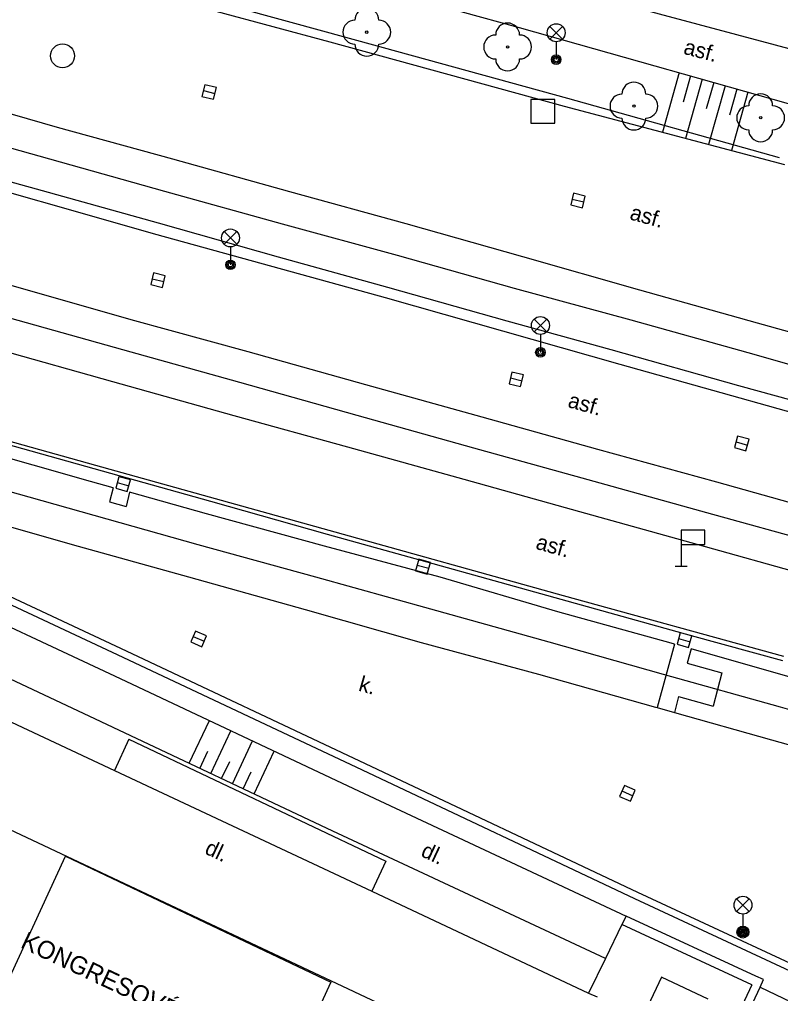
# Model space of a CAD drawing. Extents: x -600309 to -598967, y -1161267 to -1160292.
# Drawn here: x -599908.39 to -599876.57, y -1161220.83 to -1161180.1 of the extents above; entities that cross this region are included whole.
import ezdxf

# ---------------------------------------------------------------- set-up
doc = ezdxf.new("R2010")
doc.units = 0
for name, color, linetype in [('Level 11', 7, 'Continuous'), ('Level 13', 7, 'Continuous'), ('Level 14', 7, 'Continuous'), ('Level 15', 7, 'Continuous'), ('Level 22', 7, 'Continuous'), ('Level 25', 7, 'Continuous'), ('Level 26', 7, 'Continuous'), ('Level 27', 7, 'Continuous'), ('Level 33', 7, 'Continuous'), ('Level 34', 7, 'Continuous'), ('Level 40', 7, 'Continuous'), ('Level 41', 7, 'Continuous'), ('Level 5', 7, 'Continuous'), ('Level 7', 7, 'Continuous'), ('Level 9', 7, 'Continuous')]:
    doc.layers.add(name, color=color, linetype=linetype)

msp = doc.modelspace()

# ---------------------------------------------------------------- linework, layer by layer
at = {"layer": 'Level 11'}
for points in [[(-599863.64, -1161184.68), (-599889.92, -1161177.65), (-599907.2809, -1161172.7877), (-599916.52, -1161170.2), (-599932.76, -1161165.82), (-599934.95, -1161165.24), (-599946.09, -1161162.38), (-599957.33, -1161160.21), (-599967.01, -1161157.86)], [(-599930.64, -1161168.52), (-599923.55, -1161170.36), (-599921.2022, -1161171.0138), (-599908, -1161174.69), (-599894.81, -1161178.4099), (-599887.5, -1161180.43), (-599874.9699, -1161183.98)], [(-599930.45, -1161171.5), (-599922.2, -1161173.73), (-599913.48, -1161176.08), (-599904.95, -1161178.45), (-599895.42, -1161181.04), (-599885.61, -1161183.7199), (-599876.4099, -1161186.17)], [(-599939.95, -1161175.2), (-599936.36, -1161176.23), (-599931.17, -1161177.71), (-599926.29, -1161179.09), (-599921.4099, -1161180.4699), (-599916.57, -1161181.81), (-599911.32, -1161183.31), (-599906.82, -1161184.6), (-599901.99, -1161185.93), (-599897.1, -1161187.3), (-599892.24, -1161188.63), (-599887.36, -1161190.01), (-599882.46, -1161191.4), (-599877.54, -1161192.78), (-599872.64, -1161194.15), (-599870.4099, -1161194.77)], [(-599940.73, -1161177.89), (-599937.07, -1161178.9099), (-599931.93, -1161180.36), (-599927.03, -1161181.75), (-599922.07, -1161183.1599), (-599917.31, -1161184.49), (-599912.24, -1161185.93), (-599907.44, -1161187.25), (-599902.59, -1161188.61), (-599897.58, -1161190.02), (-599893, -1161191.29), (-599888.01, -1161192.7), (-599883.67, -1161193.9), (-599878.32, -1161195.4), (-599872.33, -1161197.05)], [(-599941.83, -1161181.93), (-599937.6, -1161183.12), (-599932.81, -1161184.4699), (-599927.93, -1161185.83), (-599923.11, -1161187.2), (-599918.2, -1161188.58), (-599913.23, -1161189.9699), (-599908.46, -1161191.3), (-599903.74, -1161192.64), (-599898.84, -1161193.99), (-599893.93, -1161195.37), (-599889.06, -1161196.7199), (-599884.2199, -1161198.07), (-599879.25, -1161199.44), (-599873.43, -1161201.06)], [(-599875.4699, -1161203.34), (-599880.06, -1161202.06), (-599884.96, -1161200.69), (-599889.8, -1161199.33), (-599894.6599, -1161197.99), (-599899.42, -1161196.67), (-599904.49, -1161195.25), (-599909.26, -1161193.9099), (-599913.99, -1161192.59), (-599919, -1161191.18), (-599923.76, -1161189.83), (-599928.58, -1161188.4699), (-599933.44, -1161187.11), (-599938.29, -1161185.74), (-599942.58, -1161184.57)], [(-599943.62, -1161188.24), (-599939.48, -1161189.38), (-599934.7199, -1161190.69), (-599929.63, -1161192.12), (-599924.84, -1161193.46), (-599919.9, -1161194.81), (-599915.13, -1161196.14), (-599910.12, -1161197.53), (-599905.29, -1161198.87), (-599900.4099, -1161200.24), (-599895.52, -1161201.62), (-599891.36, -1161202.78), (-599885.75, -1161204.34), (-599880.31, -1161205.86), (-599876.49, -1161206.9099)], [(-599943.57, -1161188.06), (-599943.4099, -1161188.13), (-599934.69, -1161190.53), (-599924.78, -1161193.29), (-599915.04, -1161195.99), (-599905.21, -1161198.73), (-599895.46, -1161201.46), (-599885.6599, -1161204.19), (-599876.44, -1161206.73)], [(-599904.48, -1161199.68), (-599905.42, -1161199.42), (-599910.23, -1161198.06), (-599913.13, -1161197.25)], [(-599904.48, -1161199.68), (-599904.63, -1161200.27)], [(-599903.79, -1161199.87), (-599903.93, -1161200.4699)], [(-599881, -1161206.2199), (-599881.14, -1161206.18), (-599885.88, -1161204.87), (-599890.8, -1161203.42), (-599895.64, -1161202.13), (-599900.57, -1161200.77), (-599903.79, -1161199.87)], [(-599904.63, -1161200.27), (-599903.93, -1161200.4699)], [(-599911.03, -1161200.67), (-599906.19, -1161202.06), (-599901.32, -1161203.4), (-599896.45, -1161204.77), (-599891.59, -1161206.15), (-599886.69, -1161207.48), (-599881.8, -1161208.85), (-599881.73, -1161208.87)], [(-599789.95, -1161232.9), (-599790.9699, -1161236.06), (-599800.96, -1161233.11), (-599809.71, -1161230.49), (-599818.68, -1161230.93), (-599828.53, -1161231.42), (-599840.03, -1161232.03), (-599849.05, -1161232.52), (-599855.12, -1161229.63), (-599865.36, -1161224.89), (-599873.32, -1161221.2199), (-599882.6599, -1161216.87), (-599894.05, -1161211.49), (-599904.05, -1161206.78), (-599911.83, -1161203.14), (-599911.7, -1161202.87)], [(-599789.95, -1161232.9), (-599790.24, -1161232.81), (-599791.17, -1161235.69), (-599800.87, -1161232.82), (-599809.67, -1161230.19), (-599818.7, -1161230.63), (-599828.55, -1161231.12), (-599840.05, -1161231.73), (-599848.99, -1161232.2199), (-599854.99, -1161229.36), (-599865.23, -1161224.62), (-599873.19, -1161220.95), (-599882.53, -1161216.6), (-599893.92, -1161211.2199), (-599903.92, -1161206.51), (-599911.7, -1161202.87)], [(-599881, -1161206.2199), (-599881.73, -1161208.87)], [(-599880.31, -1161206.42), (-599880.4699, -1161207.02)], [(-599876.1599, -1161207.6), (-599880.31, -1161206.42)], [(-599880.4699, -1161207.02), (-599879.02, -1161207.42)], [(-599879.02, -1161207.42), (-599879.39, -1161208.81)], [(-599880.83, -1161208.4099), (-599881, -1161209.08)], [(-599880.83, -1161208.4099), (-599879.39, -1161208.81)], [(-599881.73, -1161208.87), (-599881, -1161209.08)], [(-599881, -1161209.08), (-599876.95, -1161210.2199), (-599872.07, -1161211.59), (-599867.2, -1161212.95), (-599862.3, -1161214.31), (-599857.42, -1161215.7199), (-599852.56, -1161217.08), (-599842.77, -1161219.65)], [(-599903.82, -1161210.2), (-599904.42, -1161211.5)], [(-599903.82, -1161210.2), (-599893.07, -1161215.29)], [(-599915.56, -1161210.8), (-599886, -1161224.71)], [(-599893.07, -1161215.29), (-599893.6599, -1161216.55)], [(-599883.2, -1161217.95), (-599883.89, -1161219.36)], [(-599883.89, -1161219.36), (-599884.6, -1161220.81)], [(-599881.54, -1161220.15), (-599891.18, -1161240.58)], [(-599879.6, -1161221.06), (-599881.54, -1161220.15)], [(-599877.42, -1161220.56), (-599873.86, -1161222.27)]]:
    msp.add_lwpolyline(points, dxfattribs=at)
at = {"layer": 'Level 13'}
for points in [[(-599911.67, -1161184.6599), (-599907.14, -1161185.93), (-599902.33, -1161187.28), (-599897.4099, -1161188.64), (-599892.6, -1161189.96), (-599887.71, -1161191.33), (-599882.83, -1161192.6599), (-599877.93, -1161194.02), (-599873.05, -1161195.42), (-599867.81, -1161196.87), (-599863.07, -1161198.19), (-599858.15, -1161199.56), (-599853.34, -1161200.88), (-599848.55, -1161202.23), (-599843.71, -1161203.58), (-599838.78, -1161204.96), (-599833.98, -1161206.3), (-599829.05, -1161207.68), (-599824.28, -1161209.01), (-599814.6, -1161211.7199)], [(-599939.98, -1161191.14), (-599935.24, -1161192.5), (-599930.2199, -1161193.87), (-599925.33, -1161195.24), (-599920.48, -1161196.58), (-599915.56, -1161197.96), (-599910.63, -1161199.32), (-599905.82, -1161200.68), (-599900.94, -1161202.06), (-599896.01, -1161203.4099), (-599891.2, -1161204.75), (-599886.26, -1161206.12), (-599881.48, -1161207.48), (-599876.58, -1161208.84), (-599871.7, -1161210.24), (-599866.85, -1161211.58), (-599861.95, -1161212.96), (-599857, -1161214.35), (-599852.12, -1161215.73), (-599847.21, -1161217.08), (-599842.49, -1161218.27)], [(-599908.81, -1161192.58), (-599904.09, -1161193.9), (-599899.19, -1161195.27), (-599894.29, -1161196.65), (-599889.4099, -1161198.01), (-599884.62, -1161199.34), (-599879.6599, -1161200.7199), (-599875.02, -1161202), (-599869.7, -1161203.49), (-599864.88, -1161204.84), (-599860.39, -1161206.1), (-599855.17, -1161207.56), (-599850.4699, -1161208.87), (-599845.4699, -1161210.27), (-599840.67, -1161211.61), (-599835.69, -1161213), (-599831.84, -1161214.03)]]:
    msp.add_lwpolyline(points, dxfattribs=at)
at = {"layer": 'Level 14'}
for points in [[(-599912.06, -1161203.98), (-599904.42, -1161207.55), (-599894.43, -1161212.26), (-599883.03, -1161217.59)], [(-599883.89, -1161219.36), (-599895.29, -1161214.04), (-599904.9699, -1161209.4699), (-599912.84, -1161205.77)]]:
    msp.add_lwpolyline(points, dxfattribs=at)
at = {"layer": 'Level 15'}
for points in [[(-599880.81, -1161182.32), (-599881.51, -1161184.81)], [(-599880.33, -1161182.46), (-599880.64, -1161183.56)], [(-599879.85, -1161182.6), (-599880.54, -1161185.07)], [(-599879.36, -1161182.74), (-599879.68, -1161183.83)], [(-599878.89, -1161182.87), (-599879.58, -1161185.33)], [(-599878.4, -1161183.01), (-599878.71, -1161184.1)], [(-599877.93, -1161183.14), (-599878.62, -1161185.58)], [(-599901.3, -1161211.2), (-599900.45, -1161209.42)], [(-599900.39, -1161211.63), (-599899.55, -1161209.85)], [(-599899.49, -1161212.06), (-599898.65, -1161210.27)], [(-599900.85, -1161211.42), (-599900.51, -1161210.7)], [(-599898.58, -1161212.48), (-599897.74, -1161210.7)], [(-599899.94, -1161211.84), (-599899.6, -1161211.13)], [(-599899.04, -1161212.27), (-599898.7, -1161211.56)]]:
    msp.add_lwpolyline(points, dxfattribs=at)
at = {"layer": 'Level 22'}
for centre in [(-599893.87, -1161180.63), (-599887.98, -1161181.25), (-599882.7, -1161183.7199), (-599877.4, -1161184.21)]:
    msp.add_circle(centre, 0.05, dxfattribs=at)
for centre, start, end in [((-599893.87, -1161180.13), 0, 180), ((-599894.37, -1161180.63), 90, 270), ((-599893.37, -1161180.63), 270, 90), ((-599887.98, -1161180.75), 0, 180), ((-599888.48, -1161181.25), 90, 270), ((-599887.48, -1161181.25), 270, 90), ((-599893.87, -1161181.13), 180, 0), ((-599887.98, -1161181.75), 180, 0), ((-599882.7, -1161183.2199), 0, 180), ((-599883.2, -1161183.7199), 90, 270), ((-599882.2, -1161183.7199), 270, 90), ((-599877.4, -1161183.71), 0, 180), ((-599877.9, -1161184.21), 90, 270), ((-599876.9, -1161184.21), 270, 90), ((-599882.7, -1161184.2199), 180, 0), ((-599877.4, -1161184.71), 180, 0)]:
    msp.add_arc(centre, 0.5, start, end, dxfattribs=at)
at = {"layer": 'Level 25'}
for radius in [0.25, 0.2, 0.15, 0.1, 0.05]:
    msp.add_circle((-599878.14, -1161218.26), radius, dxfattribs=at)
at = {"layer": 'Level 26'}
msp.add_lwpolyline([(-599887.01, -1161184.44), (-599886.01, -1161184.44), (-599886.01, -1161183.44), (-599887.01, -1161183.44)], close=True, dxfattribs=at)
at = {"layer": 'Level 27'}
for p, q in [((-599900.7031, -1161183.0715), (-599900.2169, -1161183.1885)), ((-599885.2831, -1161187.6115), (-599884.7969, -1161187.7285)), ((-599902.8431, -1161190.9415), (-599902.3569, -1161191.0585)), ((-599887.8631, -1161195.0915), (-599887.3769, -1161195.2085)), ((-599878.4308, -1161197.7629), (-599877.9492, -1161197.8971)), ((-599904.3008, -1161199.4629), (-599903.8192, -1161199.5971)), ((-599891.7608, -1161202.9129), (-599891.2792, -1161203.0471)), ((-599901.1294, -1161205.9005), (-599900.6706, -1161206.0995)), ((-599880.8308, -1161205.9829), (-599880.3492, -1161206.1171)), ((-599883.1993, -1161212.3605), (-599882.7405, -1161212.5595))]:
    msp.add_line(p, q, dxfattribs=at)
for points in [[(-599900.7616, -1161183.3145), (-599900.2755, -1161183.4316), (-599900.1584, -1161182.9455), (-599900.6445, -1161182.8284)], [(-599885.3416, -1161187.8545), (-599884.8555, -1161187.9716), (-599884.7384, -1161187.4855), (-599885.2245, -1161187.3684)], [(-599902.9016, -1161191.1845), (-599902.4155, -1161191.3016), (-599902.2984, -1161190.8155), (-599902.7845, -1161190.6984)], [(-599887.9216, -1161195.3345), (-599887.4355, -1161195.4516), (-599887.3184, -1161194.9655), (-599887.8045, -1161194.8484)], [(-599878.498, -1161198.0037), (-599878.0163, -1161198.138), (-599877.882, -1161197.6563), (-599878.3637, -1161197.522)], [(-599904.368, -1161199.7037), (-599903.8863, -1161199.838), (-599903.752, -1161199.3563), (-599904.2337, -1161199.222)], [(-599891.828, -1161203.1537), (-599891.3463, -1161203.288), (-599891.212, -1161202.8063), (-599891.6937, -1161202.672)], [(-599901.2288, -1161206.1299), (-599900.7701, -1161206.3288), (-599900.5712, -1161205.8701), (-599901.0299, -1161205.6712)], [(-599880.898, -1161206.2237), (-599880.4163, -1161206.358), (-599880.282, -1161205.8763), (-599880.7637, -1161205.742)], [(-599883.2987, -1161212.5899), (-599882.84, -1161212.7888), (-599882.6411, -1161212.3301), (-599883.0998, -1161212.1312)]]:
    msp.add_lwpolyline(points, close=True, dxfattribs=at)
msp.add_circle((-599906.59, -1161181.62), 0.5, dxfattribs=at)
at = {"layer": 'Level 33'}
for p, q in [((-599886.215, -1161180.92), (-599885.685, -1161180.39)), ((-599886.215, -1161180.39), (-599885.685, -1161180.92)), ((-599885.95, -1161181.03), (-599885.95, -1161181.78)), ((-599899.835, -1161189.5), (-599899.305, -1161188.97)), ((-599899.835, -1161188.97), (-599899.305, -1161189.5)), ((-599899.57, -1161189.61), (-599899.57, -1161190.36)), ((-599886.875, -1161193.16), (-599886.345, -1161192.63)), ((-599886.875, -1161192.63), (-599886.345, -1161193.16)), ((-599886.61, -1161193.27), (-599886.61, -1161194.02)), ((-599878.405, -1161217.4), (-599877.875, -1161216.87)), ((-599878.405, -1161216.87), (-599877.875, -1161217.4)), ((-599878.14, -1161217.51), (-599878.14, -1161218.26))]:
    msp.add_line(p, q, dxfattribs=at)
for centre, radius in [((-599885.95, -1161180.655), 0.375), ((-599885.95, -1161181.78), 0.2), ((-599885.95, -1161181.78), 0.1445), ((-599885.95, -1161181.78), 0.0876), ((-599899.57, -1161189.235), 0.375), ((-599899.57, -1161190.36), 0.2), ((-599899.57, -1161190.36), 0.1445), ((-599899.57, -1161190.36), 0.0876), ((-599886.61, -1161192.895), 0.375), ((-599886.61, -1161194.02), 0.2), ((-599886.61, -1161194.02), 0.1445), ((-599886.61, -1161194.02), 0.0876), ((-599878.14, -1161217.135), 0.375)]:
    msp.add_circle(centre, radius, dxfattribs=at)
at = {"layer": 'Level 34'}
for p, q in [((-599880.73, -1161202.06), (-599880.73, -1161202.96)), ((-599880.98, -1161202.96), (-599880.48, -1161202.96))]:
    msp.add_line(p, q, dxfattribs=at)
msp.add_lwpolyline([(-599880.73, -1161202.06), (-599879.73, -1161202.06), (-599879.73, -1161201.46), (-599880.73, -1161201.46)], close=True, dxfattribs=at)
at = {"layer": 'Level 5'}
for points in [[(-599913.49, -1161207.25), (-599904.42, -1161211.5)], [(-599904.42, -1161211.5), (-599893.6599, -1161216.55)], [(-599924.52, -1161254.29), (-599906.4699, -1161215.09)], [(-599906.4699, -1161215.09), (-599895.37, -1161220.36)], [(-599893.6599, -1161216.55), (-599884.6, -1161220.81)], [(-599895.37, -1161220.36), (-599913.37, -1161259.43)], [(-599884.6, -1161220.81), (-599884.24, -1161220.9699)]]:
    msp.add_lwpolyline(points, dxfattribs=at)
at = {"layer": 'Level 7'}
for points in [[(-599883.03, -1161217.59), (-599883.2, -1161217.95)], [(-599877.6, -1161220.1), (-599883.03, -1161217.59)], [(-599877.77, -1161220.46), (-599883.2, -1161217.95)], [(-599877.42, -1161220.56), (-599877.28, -1161220.25), (-599877.6, -1161220.1)], [(-599877.77, -1161220.46), (-599882.83, -1161231.29)], [(-599879.48, -1161224.9699), (-599877.42, -1161220.56)]]:
    msp.add_lwpolyline(points, dxfattribs=at)
at = {"layer": 'Level 9'}
for points in [[(-599930.23, -1161171.07), (-599922.02, -1161173.29), (-599913.53, -1161175.67), (-599904.8, -1161178.08), (-599895.57, -1161180.62), (-599885.48, -1161183.39), (-599876.62, -1161185.87)], [(-599940.35, -1161178.54), (-599932.09, -1161180.79), (-599922.17, -1161183.52), (-599912.43, -1161186.31), (-599902.65, -1161189.09), (-599893.1, -1161191.7199), (-599883.29, -1161194.52), (-599872.46, -1161197.55)]]:
    msp.add_lwpolyline(points, dxfattribs=at)

# ---------------------------------------------------------------- texts
at = {"layer": 'Level 40'}
for s, rotation, p in [('asf.', 345.23, (-599880.6599, -1161181.53)), ('asf.', 344.48, (-599882.9099, -1161188.45)), ('asf.', 344.48, (-599885.5, -1161196.3)), ('asf.', 344.48, (-599886.84, -1161202.23)), ('k.', 344.16, (-599894.25, -1161208.1599)), ('dl.', 334.87, (-599900.69, -1161214.96)), ('dl.', 334.87, (-599891.65, -1161215.07))]:
    msp.add_text(s, height=0.65, rotation=rotation, dxfattribs=at).set_placement(p)
at = {"layer": 'Level 41'}
msp.add_text('KONGRESOVÉ CENTRUM', height=0.75, rotation=334.77, dxfattribs=at).set_placement((-599908.39, -1161218.89))

doc.saveas('drawing.dxf')
